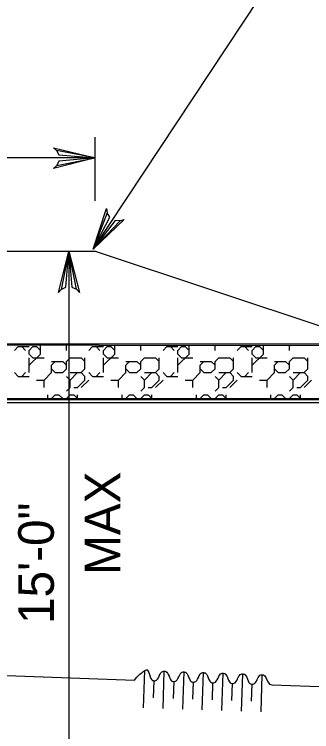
# Model space of a CAD drawing. Extents: x 636462 to 639890, y 299944 to 300538.
# Drawn here: x 638448.9 to 638473.9, y 300374.6 to 300434.9 of the extents above; entities that cross this region are included whole.
import ezdxf

# ---------------------------------------------------------------- set-up
doc = ezdxf.new("R2010")
doc.units = 0
doc.layers.add('Default', color=7, linetype='Continuous')

msp = doc.modelspace()

# ---------------------------------------------------------------- linework, layer by layer
at = {"layer": 'Default'}
for p, q in [((638455.502, 300415.181), (638471.693, 300439.652)), ((638455.666, 300419.243), (638455.666, 300424.607)), ((638455.666, 300422.862), (638413.193, 300422.862)), ((638453.465, 300415.029), (638453.465, 300371.052)), ((638455.666, 300415.029), (638576.237, 300374.838)), ((638448.885, 300406.67), (638449.197, 300406.983)), ((638449.197, 300406.983), (638450.134, 300406.983)), ((638449.822, 300406.67), (638449.509, 300406.983)), ((638450.134, 300406.67), (638450.446, 300406.983)), ((638450.446, 300406.983), (638450.759, 300406.983)), ((638451.071, 300406.67), (638450.759, 300406.983)), ((638451.071, 300406.358), (638451.071, 300407.109)), ((638453.257, 300406.67), (638453.257, 300407.106)), ((638455.131, 300406.67), (638455.443, 300406.983)), ((638455.443, 300406.983), (638456.38, 300406.983)), ((638456.068, 300406.67), (638455.755, 300406.983)), ((638456.38, 300406.67), (638456.692, 300406.983)), ((638456.692, 300406.983), (638457.004, 300406.983)), ((638457.317, 300406.67), (638457.004, 300406.983)), ((638457.317, 300406.358), (638457.317, 300407.101)), ((638459.503, 300406.67), (638459.503, 300407.098)), ((638461.377, 300406.67), (638461.689, 300406.983)), ((638461.689, 300406.983), (638462.626, 300406.983)), ((638462.313, 300406.67), (638462.001, 300406.983)), ((638462.626, 300406.67), (638462.938, 300406.983)), ((638462.938, 300406.983), (638463.25, 300406.983)), ((638463.563, 300406.67), (638463.25, 300406.983)), ((638463.563, 300406.358), (638463.563, 300407.092)), ((638465.749, 300406.67), (638465.749, 300407.089)), ((638467.623, 300406.67), (638467.935, 300406.983)), ((638467.935, 300406.983), (638468.872, 300406.983)), ((638468.559, 300406.67), (638468.247, 300406.983)), ((638468.872, 300406.67), (638469.184, 300406.983)), ((638469.184, 300406.983), (638469.496, 300406.983)), ((638469.809, 300406.67), (638469.496, 300406.983)), ((638469.809, 300406.358), (638469.809, 300407.084)), ((638471.995, 300406.67), (638471.995, 300407.081)), ((638450.134, 300406.358), (638450.134, 300406.67)), ((638450.446, 300406.046), (638450.134, 300406.358)), ((638450.134, 300405.421), (638451.071, 300406.358)), ((638456.38, 300406.358), (638456.38, 300406.67)), ((638456.692, 300406.046), (638456.38, 300406.358)), ((638456.38, 300405.421), (638457.317, 300406.358)), ((638462.626, 300406.358), (638462.626, 300406.67)), ((638462.938, 300406.046), (638462.626, 300406.358)), ((638462.626, 300405.421), (638463.563, 300406.358)), ((638468.872, 300406.358), (638468.872, 300406.67)), ((638469.184, 300406.046), (638468.872, 300406.358)), ((638468.872, 300405.421), (638469.809, 300406.358)), ((638450.134, 300404.797), (638450.134, 300406.046)), ((638450.446, 300406.046), (638451.383, 300406.046)), ((638452.008, 300405.421), (638452.32, 300405.733)), ((638452.008, 300405.733), (638452.945, 300405.733)), ((638453.257, 300405.421), (638452.945, 300405.733)), ((638453.257, 300405.733), (638453.569, 300406.046)), ((638453.257, 300405.109), (638453.257, 300405.733)), ((638453.569, 300406.046), (638454.506, 300406.046)), ((638454.818, 300405.733), (638454.506, 300406.046)), ((638454.818, 300405.109), (638454.818, 300406.046)), ((638456.38, 300404.797), (638456.38, 300406.046)), ((638456.692, 300406.046), (638457.629, 300406.046)), ((638458.254, 300405.421), (638458.566, 300405.733)), ((638458.254, 300405.733), (638459.191, 300405.733)), ((638459.503, 300405.421), (638459.191, 300405.733)), ((638459.503, 300405.733), (638459.815, 300406.046)), ((638459.503, 300405.109), (638459.503, 300405.733)), ((638459.815, 300406.046), (638460.752, 300406.046)), ((638461.064, 300405.733), (638460.752, 300406.046)), ((638461.064, 300405.109), (638461.064, 300406.046)), ((638462.626, 300404.797), (638462.626, 300406.046)), ((638462.938, 300406.046), (638463.875, 300406.046)), ((638464.5, 300405.421), (638464.812, 300405.733)), ((638464.5, 300405.733), (638465.436, 300405.733)), ((638465.749, 300405.421), (638465.436, 300405.733)), ((638465.749, 300405.733), (638466.061, 300406.046)), ((638465.749, 300405.109), (638465.749, 300405.733)), ((638466.061, 300406.046), (638466.998, 300406.046)), ((638467.31, 300405.733), (638466.998, 300406.046)), ((638467.31, 300405.109), (638467.31, 300406.046)), ((638468.872, 300404.797), (638468.872, 300406.046)), ((638469.184, 300406.046), (638470.121, 300406.046)), ((638470.745, 300405.421), (638471.058, 300405.733)), ((638470.745, 300405.733), (638471.682, 300405.733)), ((638471.995, 300405.421), (638471.682, 300405.733)), ((638471.995, 300405.733), (638472.307, 300406.046)), ((638471.995, 300405.109), (638471.995, 300405.733)), ((638472.307, 300406.046), (638473.244, 300406.046)), ((638473.556, 300405.733), (638473.244, 300406.046)), ((638473.556, 300405.109), (638473.556, 300406.046)), ((638452.008, 300404.797), (638452.008, 300405.421)), ((638452.32, 300404.797), (638452.008, 300405.109)), ((638452.945, 300404.797), (638453.257, 300405.109)), ((638454.506, 300404.797), (638454.818, 300405.109)), ((638458.254, 300404.797), (638458.254, 300405.421)), ((638458.566, 300404.797), (638458.254, 300405.109)), ((638459.191, 300404.797), (638459.503, 300405.109)), ((638460.752, 300404.797), (638461.064, 300405.109)), ((638464.5, 300404.797), (638464.5, 300405.421)), ((638464.812, 300404.797), (638464.5, 300405.109)), ((638465.436, 300404.797), (638465.749, 300405.109)), ((638466.998, 300404.797), (638467.31, 300405.109)), ((638470.745, 300404.797), (638470.745, 300405.421)), ((638471.058, 300404.797), (638470.745, 300405.109)), ((638471.682, 300404.797), (638471.995, 300405.109)), ((638473.244, 300404.797), (638473.556, 300405.109)), ((638449.197, 300404.484), (638448.885, 300404.797)), ((638449.197, 300404.484), (638450.134, 300404.484)), ((638449.509, 300404.484), (638449.822, 300404.797)), ((638451.383, 300404.172), (638452.008, 300404.797)), ((638452.32, 300404.797), (638452.945, 300404.797)), ((638453.569, 300404.172), (638453.257, 300404.484)), ((638453.569, 300404.172), (638454.194, 300404.797)), ((638453.569, 300404.797), (638454.506, 300404.797)), ((638454.818, 300404.484), (638454.506, 300404.797)), ((638454.818, 300404.172), (638454.818, 300404.484)), ((638455.443, 300404.484), (638455.131, 300404.797)), ((638455.443, 300404.484), (638456.38, 300404.484)), ((638455.755, 300404.484), (638456.068, 300404.797)), ((638457.629, 300404.172), (638458.254, 300404.797)), ((638458.566, 300404.797), (638459.191, 300404.797)), ((638459.815, 300404.172), (638459.503, 300404.484)), ((638459.815, 300404.172), (638460.44, 300404.797)), ((638459.815, 300404.797), (638460.752, 300404.797)), ((638461.064, 300404.484), (638460.752, 300404.797)), ((638461.064, 300404.172), (638461.064, 300404.484)), ((638461.689, 300404.484), (638461.377, 300404.797)), ((638461.689, 300404.484), (638462.626, 300404.484)), ((638462.001, 300404.484), (638462.313, 300404.797)), ((638463.875, 300404.172), (638464.5, 300404.797)), ((638464.812, 300404.797), (638465.436, 300404.797)), ((638466.061, 300404.172), (638465.749, 300404.484)), ((638466.061, 300404.172), (638466.686, 300404.797)), ((638466.061, 300404.797), (638466.998, 300404.797)), ((638467.31, 300404.484), (638466.998, 300404.797)), ((638467.31, 300404.172), (638467.31, 300404.484)), ((638467.935, 300404.484), (638467.623, 300404.797)), ((638467.935, 300404.484), (638468.872, 300404.484)), ((638468.247, 300404.484), (638468.559, 300404.797)), ((638470.121, 300404.172), (638470.745, 300404.797)), ((638471.058, 300404.797), (638471.682, 300404.797)), ((638472.307, 300404.172), (638471.995, 300404.484)), ((638472.307, 300404.172), (638472.932, 300404.797)), ((638472.307, 300404.797), (638473.244, 300404.797)), ((638473.556, 300404.484), (638473.244, 300404.797)), ((638473.556, 300404.172), (638473.556, 300404.484)), ((638450.759, 300404.172), (638451.383, 300404.172)), ((638451.383, 300403.547), (638451.383, 300404.172)), ((638453.569, 300403.547), (638453.569, 300404.172)), ((638454.194, 300403.547), (638454.818, 300404.172)), ((638454.506, 300403.547), (638455.131, 300404.172)), ((638457.004, 300404.172), (638457.629, 300404.172)), ((638457.629, 300403.547), (638457.629, 300404.172)), ((638459.815, 300403.547), (638459.815, 300404.172)), ((638460.44, 300403.547), (638461.064, 300404.172)), ((638460.752, 300403.547), (638461.377, 300404.172)), ((638463.25, 300404.172), (638463.875, 300404.172)), ((638463.875, 300403.547), (638463.875, 300404.172)), ((638466.061, 300403.547), (638466.061, 300404.172)), ((638466.686, 300403.547), (638467.31, 300404.172)), ((638466.998, 300403.547), (638467.623, 300404.172)), ((638469.496, 300404.172), (638470.121, 300404.172)), ((638470.121, 300403.547), (638470.121, 300404.172)), ((638472.307, 300403.547), (638472.307, 300404.172)), ((638472.932, 300403.547), (638473.556, 300404.172)), ((638473.244, 300403.547), (638473.868, 300404.172)), ((638453.257, 300403.235), (638453.569, 300403.547)), ((638453.881, 300403.547), (638454.194, 300403.547)), ((638459.503, 300403.235), (638459.815, 300403.547)), ((638460.127, 300403.547), (638460.44, 300403.547)), ((638465.749, 300403.235), (638466.061, 300403.547)), ((638466.373, 300403.547), (638466.686, 300403.547)), ((638471.995, 300403.235), (638472.307, 300403.547)), ((638472.619, 300403.547), (638472.932, 300403.547)), ((638451.695, 300402.594), (638451.695, 300402.923)), ((638452.008, 300402.61), (638452.32, 300402.923)), ((638452.008, 300402.594), (638452.008, 300402.61)), ((638452.32, 300402.923), (638452.632, 300402.923)), ((638452.945, 300402.61), (638452.632, 300402.923)), ((638452.945, 300402.594), (638452.945, 300402.61)), ((638453.257, 300402.61), (638453.569, 300402.923)), ((638453.569, 300402.923), (638453.881, 300402.923)), ((638454.194, 300402.61), (638453.881, 300402.923)), ((638454.194, 300402.594), (638454.194, 300402.923)), ((638457.941, 300402.592), (638457.941, 300402.923)), ((638458.254, 300402.61), (638458.566, 300402.923)), ((638458.254, 300402.592), (638458.254, 300402.61)), ((638458.566, 300402.923), (638458.878, 300402.923)), ((638459.191, 300402.61), (638458.878, 300402.923)), ((638459.191, 300402.592), (638459.191, 300402.61)), ((638459.503, 300402.61), (638459.815, 300402.923)), ((638459.815, 300402.923), (638460.127, 300402.923)), ((638460.44, 300402.61), (638460.127, 300402.923)), ((638460.44, 300402.592), (638460.44, 300402.923)), ((638464.187, 300402.59), (638464.187, 300402.923)), ((638464.5, 300402.61), (638464.812, 300402.923)), ((638464.5, 300402.59), (638464.5, 300402.61)), ((638464.812, 300402.923), (638465.124, 300402.923)), ((638465.436, 300402.61), (638465.124, 300402.923)), ((638465.436, 300402.59), (638465.436, 300402.61)), ((638465.749, 300402.61), (638466.061, 300402.923)), ((638466.061, 300402.923), (638466.373, 300402.923)), ((638466.686, 300402.61), (638466.373, 300402.923)), ((638466.686, 300402.59), (638466.686, 300402.923)), ((638470.433, 300402.589), (638470.433, 300402.923)), ((638470.745, 300402.61), (638471.058, 300402.923)), ((638470.745, 300402.588), (638470.745, 300402.61)), ((638471.058, 300402.923), (638471.37, 300402.923)), ((638471.682, 300402.61), (638471.37, 300402.923)), ((638471.682, 300402.588), (638471.682, 300402.61)), ((638471.995, 300402.61), (638472.307, 300402.923)), ((638472.307, 300402.923), (638472.619, 300402.923)), ((638472.932, 300402.61), (638472.619, 300402.923)), ((638472.932, 300402.588), (638472.932, 300402.923)), ((638345.119, 300382.909), (638458.986, 300378.933)), ((638459.73, 300376.597), (638459.839, 300379.728)), ((638461.377, 300376.539), (638461.487, 300379.671)), ((638463.133, 300379.613), (638463.023, 300376.482)), ((638464.671, 300376.424), (638464.781, 300379.555)), ((638466.319, 300376.366), (638466.428, 300379.498)), ((638467.967, 300376.309), (638468.076, 300379.44)), ((638469.615, 300376.251), (638469.724, 300379.383)), ((638460.584, 300377.44), (638460.634, 300378.875)), ((638462.28, 300378.818), (638462.23, 300377.382)), ((638463.878, 300377.323), (638463.928, 300378.76)), ((638465.526, 300377.265), (638465.576, 300378.703)), ((638467.174, 300377.21), (638467.224, 300378.645)), ((638468.821, 300377.15), (638468.872, 300378.588)), ((638470.52, 300378.53), (638582.339, 300374.625))]:
    msp.add_line(p, q, dxfattribs=at)
for points in [[(638452.434, 300423.5), (638452.165, 300423.723), (638455.666, 300422.862), (638452.434, 300423.5), (638452.63, 300423.127), (638455.666, 300422.862), (638452.636, 300422.603), (638452.454, 300422.228), (638455.666, 300422.862), (638452.171, 300421.974), (638452.454, 300422.228)], [(638457.776, 300417.565), (638458.109, 300417.672), (638455.502, 300415.181), (638457.776, 300417.565), (638457.356, 300417.599), (638455.502, 300415.181), (638456.911, 300417.875), (638456.692, 300418.231), (638455.502, 300415.181), (638456.63, 300418.605), (638456.692, 300418.231)], [(638319.504, 300383.799), (638413.193, 300415.029), (638434.429, 300415.029), (638455.666, 300415.029)], [(638452.828, 300411.797), (638452.604, 300411.528), (638453.465, 300415.029), (638452.828, 300411.797), (638453.201, 300411.993), (638453.465, 300415.029), (638453.724, 300411.999), (638454.1, 300411.817), (638453.465, 300415.029), (638454.353, 300411.534), (638454.1, 300411.817)], [(638389.771, 300407.221), (638434.429, 300407.221), (638479.088, 300407.221)], [(638409.46, 300407.019), (638417.6, 300402.288), (638478.297, 300402.288), (638558.272, 300375.493)], [(638417.651, 300402.537), (638434.429, 300402.537), (638478.328, 300402.537), (638559.69, 300375.416)]]:
    msp.add_lwpolyline(points, dxfattribs=at)
msp.add_lwpolyline([(638409.872, 300407.166), (638479.046, 300407.071), (638574.957, 300375.042), (638559.723, 300375.582), (638478.369, 300402.586), (638417.7, 300402.605)], close=True, dxfattribs=at)
msp.add_open_spline([(638458.986, 300378.933), (638459.274, 300379.29), (638459.557, 300379.543), (638459.839, 300379.728), (638460.12, 300379.913), (638460.359, 300378.885), (638460.634, 300378.875), (638460.909, 300378.866), (638461.212, 300379.68), (638461.487, 300379.671), (638461.761, 300379.661), (638462.006, 300378.828), (638462.28, 300378.818), (638462.555, 300378.808), (638462.858, 300379.623), (638463.133, 300379.613), (638463.407, 300379.603), (638463.653, 300378.77), (638463.928, 300378.76), (638464.202, 300378.751), (638464.506, 300379.565), (638464.781, 300379.555), (638465.055, 300379.546), (638465.301, 300378.712), (638465.576, 300378.703), (638465.85, 300378.693), (638466.154, 300379.508), (638466.428, 300379.498), (638466.703, 300379.488), (638466.949, 300378.655), (638467.224, 300378.645), (638467.498, 300378.636), (638467.802, 300379.45), (638468.076, 300379.44), (638468.351, 300379.431), (638468.597, 300378.597), (638468.872, 300378.588), (638469.146, 300378.578), (638469.45, 300379.392), (638469.724, 300379.383), (638469.999, 300379.373), (638470.243, 300378.488), (638470.52, 300378.53)], degree=3, dxfattribs=at)

# ---------------------------------------------------------------- texts
for s, p in [('MAX', (638457.801, 300387.781)), ('15\'-0"', (638452.203, 300383.652))]:
    msp.add_text(s, height=2.998, rotation=90, dxfattribs=at).set_placement(p)

doc.saveas('drawing.dxf')
